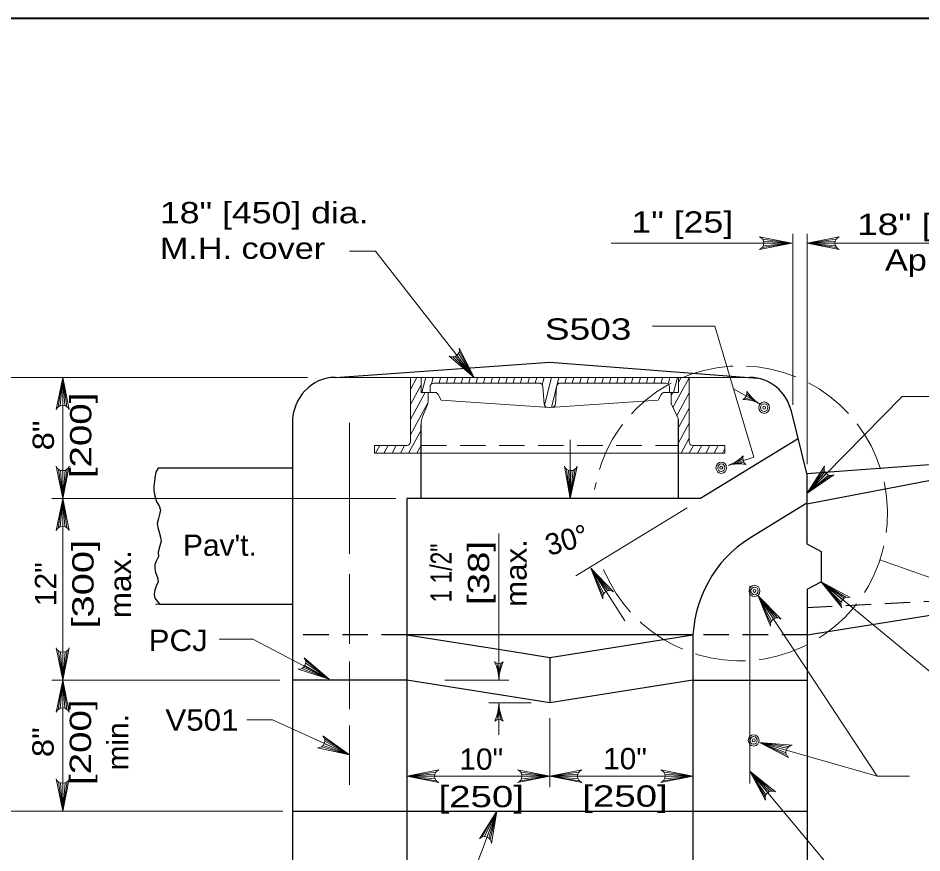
# Model space of a CAD drawing. Extents: x 339.1 to 373.1, y 1412.7 to 1456.7.
# Drawn here: x 342.65 to 349.27, y 1428.13 to 1434.25 of the extents above; entities that cross this region are included whole.
import ezdxf
from ezdxf.enums import TextEntityAlignment as Align

# ---------------------------------------------------------------- set-up
doc = ezdxf.new("R2010")
doc.units = 0
doc.header["$LTSCALE"] = 0.062
doc.linetypes.add('LONG_DASHED', pattern=[7.5, 6, -1.5])
doc.linetypes.add('MEDIUM_DASHED', pattern=[4.5, 3, -1.5])
doc.layers.add('1', color=7, linetype='Continuous', lineweight=13)

msp = doc.modelspace()

# ---------------------------------------------------------------- linework, layer by layer
at = {"layer": '1', "lineweight": 25}
for p, q in [((341.0605, 1434.2455), (372.5605, 1434.2455)), ((344.96875, 1431.61425), (346.53958, 1431.72508)), ((346.53958, 1431.72508), (348.06092, 1431.609)), ((348.42217, 1430.91067), (348.309, 1431.36625)), ((344.65467, 1431.28167), (344.65467, 1430.23983)), ((347.48167, 1430.72742), (347.48167, 1431.30608)), ((345.597, 1430.72742), (345.597, 1431.27)), ((348.35358, 1431.16217), (347.64233, 1430.72742)), ((348.42217, 1430.68892), (350.30792, 1431.04758)), ((348.42217, 1430.91067), (350.30792, 1431.04758)), ((344.65467, 1430.94908), (343.67008, 1430.94908)), ((348.42217, 1430.91067), (348.42217, 1430.39483)), ((345.49225, 1430.72742), (345.49225, 1426.24892)), ((347.64233, 1430.72742), (345.49225, 1430.72742)), ((348.42217, 1430.69225), (348.005, 1430.43717)), ((348.42217, 1430.39483), (348.52783, 1430.339)), ((348.52783, 1430.339), (348.52783, 1430.11725)), ((348.424, 1430.06225), (348.52783, 1430.11725)), ((348.424, 1430.06225), (348.424, 1425.36217)), ((348.424, 1429.72975), (350.30775, 1430.02767)), ((344.65467, 1429.95142), (343.68225, 1429.95142)), ((346.53925, 1429.56342), (347.58642, 1429.72975)), ((346.53925, 1429.56342), (346.53925, 1429.23092)), ((345.49225, 1429.39717), (344.65433, 1429.39717)), ((346.53933, 1429.23092), (345.49225, 1429.39717)), ((347.58642, 1429.39717), (346.53925, 1429.23092)), ((347.58642, 1429.39717), (348.42417, 1429.39717)), ((344.65467, 1428.43842), (348.424, 1428.43842))]:
    msp.add_line(p, q, dxfattribs=at)
at = {"layer": '1'}
for p, q in [((348.098, 1432.62742), (348.31125, 1432.59758)), ((348.10517, 1432.61267), (348.31125, 1432.59758)), ((348.31933, 1431.41267), (348.31933, 1432.665)), ((348.424, 1430.9775), (348.424, 1432.665)), ((348.63733, 1432.62742), (348.424, 1432.59758)), ((348.63008, 1432.61267), (348.424, 1432.59758)), ((346.99033, 1432.59758), (348.31125, 1432.59758)), ((348.0955, 1432.56458), (348.31125, 1432.59758)), ((348.10367, 1432.57842), (348.31125, 1432.59758)), ((348.10742, 1432.59758), (348.31125, 1432.59758)), ((348.424, 1432.59758), (349.80033, 1432.59758)), ((348.62792, 1432.59758), (348.424, 1432.59758)), ((348.63167, 1432.57842), (348.424, 1432.59758)), ((348.63983, 1432.56458), (348.424, 1432.59758)), ((347.74825, 1431.99017), (347.29283, 1431.99017)), ((348.03492, 1431.02983), (347.74825, 1431.99017)), ((345.82975, 1431.76392), (345.98458, 1431.61425)), ((345.84583, 1431.76733), (345.98458, 1431.61425)), ((345.85908, 1431.77483), (345.98458, 1431.61425)), ((345.87183, 1431.78967), (345.98458, 1431.61425)), ((345.87775, 1431.80458), (345.98458, 1431.61425)), ((344.76575, 1431.61425), (342.21133, 1431.61425)), ((342.93883, 1431.39842), (342.97183, 1431.61425)), ((342.95267, 1431.40658), (342.97183, 1431.61425)), ((342.97183, 1430.94633), (342.97183, 1431.61425)), ((342.97183, 1431.41033), (342.97183, 1431.61425)), ((342.98683, 1431.40817), (342.97183, 1431.61425)), ((343.00167, 1431.40092), (342.97183, 1431.61425)), ((348.00525, 1431.61425), (344.96875, 1431.61425)), ((345.5185, 1431.14308), (345.5185, 1431.61425)), ((345.5185, 1431.52658), (345.56633, 1431.61425)), ((345.597, 1431.50342), (345.597, 1431.61425)), ((345.60317, 1431.50342), (345.631, 1431.61333)), ((345.67375, 1431.56767), (345.68558, 1431.61425)), ((345.72917, 1431.57267), (345.73958, 1431.61425)), ((345.78333, 1431.57267), (345.79392, 1431.61425)), ((345.8375, 1431.57267), (345.848, 1431.61425)), ((345.89167, 1431.57267), (345.90217, 1431.61425)), ((345.94583, 1431.57267), (345.95633, 1431.61425)), ((346.00008, 1431.57267), (346.01058, 1431.61425)), ((346.05425, 1431.57267), (346.06483, 1431.61425)), ((346.10833, 1431.57267), (346.11892, 1431.61425)), ((346.16258, 1431.57267), (346.17317, 1431.61425)), ((346.21683, 1431.57267), (346.22742, 1431.61425)), ((346.27108, 1431.57267), (346.28158, 1431.61425)), ((346.32525, 1431.57267), (346.33575, 1431.61425)), ((346.37942, 1431.57267), (346.39, 1431.61433)), ((346.43367, 1431.57267), (346.44425, 1431.61425)), ((346.48475, 1431.55992), (346.49833, 1431.61358)), ((346.50083, 1431.40975), (346.5525, 1431.61392)), ((346.55117, 1431.39433), (346.60633, 1431.61233)), ((346.6505, 1431.57267), (346.661, 1431.61425)), ((346.70458, 1431.57267), (346.71517, 1431.61425)), ((346.759, 1431.57267), (346.7695, 1431.61425)), ((346.81317, 1431.57267), (346.82358, 1431.61425)), ((346.86717, 1431.57267), (346.87775, 1431.61425)), ((346.9215, 1431.57267), (346.932, 1431.61425)), ((346.97575, 1431.57267), (346.98625, 1431.61425)), ((347.03, 1431.57267), (347.04042, 1431.61425)), ((347.08408, 1431.57267), (347.09467, 1431.61425)), ((347.13833, 1431.57267), (347.14892, 1431.61425)), ((347.1925, 1431.57267), (347.203, 1431.61375)), ((347.24675, 1431.57267), (347.25692, 1431.61292)), ((347.30075, 1431.57267), (347.31133, 1431.61425)), ((347.355, 1431.57267), (347.3655, 1431.614)), ((347.40742, 1431.56567), (347.41958, 1431.61358)), ((347.44158, 1431.39417), (347.56025, 1431.6115)), ((347.44592, 1431.50342), (347.47392, 1431.61425)), ((347.48167, 1431.50342), (347.48167, 1431.61425)), ((347.48167, 1431.57875), (347.50108, 1431.61425)), ((347.56025, 1431.14308), (347.56025, 1431.61425)), ((345.5185, 1431.41558), (345.597, 1431.5595)), ((345.66242, 1431.50342), (345.66242, 1431.54492)), ((346.46267, 1431.57267), (345.68858, 1431.57267)), ((346.48883, 1431.54708), (346.49817, 1431.41817)), ((346.58983, 1431.54708), (346.5805, 1431.41817)), ((347.39008, 1431.57267), (346.616, 1431.57267)), ((347.41625, 1431.50342), (347.41625, 1431.54492)), ((345.5185, 1431.30483), (345.62683, 1431.50342)), ((345.69967, 1431.50342), (345.597, 1431.50342)), ((345.64933, 1431.4595), (345.64933, 1431.50342)), ((345.72233, 1431.4895), (345.74508, 1431.44792)), ((347.35633, 1431.4895), (347.33367, 1431.44792)), ((347.48167, 1431.50342), (347.37917, 1431.50342)), ((347.42933, 1431.42358), (347.42933, 1431.50342)), ((347.42975, 1431.48342), (347.44008, 1431.5025)), ((347.46967, 1431.33492), (347.56025, 1431.50075)), ((348.08, 1431.4195), (347.88575, 1431.52958)), ((345.5185, 1431.19408), (345.64675, 1431.429)), ((345.74508, 1431.44792), (346.53767, 1431.39367)), ((347.33367, 1431.44792), (346.541, 1431.39367)), ((347.43067, 1431.41733), (347.48033, 1431.31225)), ((345.63283, 1431.38508), (345.61367, 1431.3445)), ((347.48167, 1431.24608), (347.56025, 1431.39)), ((345.0735, 1431.28167), (345.0735, 1430.32158)), ((347.48167, 1431.13525), (347.56025, 1431.27908)), ((345.50575, 1431.06), (345.597, 1431.227)), ((346.689, 1430.72742), (346.689, 1431.15717)), ((347.50108, 1431.06), (347.56025, 1431.16842)), ((345.25667, 1431.06), (345.25667, 1431.11542)), ((345.49225, 1431.11542), (345.25667, 1431.11542)), ((345.264, 1431.06), (345.29425, 1431.11542)), ((345.32442, 1431.06), (345.35467, 1431.11542)), ((345.38483, 1431.06), (345.41508, 1431.11542)), ((345.44525, 1431.06), (345.4755, 1431.11542)), ((345.56608, 1431.06), (345.597, 1431.1165)), ((347.56158, 1431.06), (347.59183, 1431.11542)), ((347.822, 1431.11542), (347.58642, 1431.11542)), ((347.622, 1431.06), (347.65225, 1431.11542)), ((347.6825, 1431.06), (347.71275, 1431.11542)), ((347.74292, 1431.06), (347.77317, 1431.11542)), ((347.80358, 1431.06042), (347.822, 1431.09425)), ((347.822, 1431.06), (347.822, 1431.11542)), ((347.822, 1431.06), (345.25667, 1431.06)), ((347.84567, 1430.96975), (348.03492, 1431.02983)), ((342.94192, 1430.94067), (342.97183, 1430.72742)), ((342.95675, 1430.9335), (342.97183, 1430.72742)), ((343.00475, 1430.94325), (342.97183, 1430.72742)), ((342.991, 1430.935), (342.97183, 1430.72742)), ((342.97183, 1430.93125), (342.97183, 1430.72742)), ((346.66308, 1430.94125), (346.689, 1430.72742)), ((346.67775, 1430.93375), (346.689, 1430.72742)), ((346.726, 1430.94258), (346.689, 1430.72742)), ((346.712, 1430.93467), (346.689, 1430.72742)), ((346.69275, 1430.93125), (346.689, 1430.72742)), ((348.54967, 1430.93717), (348.42217, 1430.76358)), ((348.55517, 1430.92167), (348.42217, 1430.76358)), ((348.56442, 1430.90958), (348.42217, 1430.76358)), ((348.58075, 1430.89892), (348.42217, 1430.76358)), ((348.59642, 1430.89517), (348.42217, 1430.76358)), ((345.41283, 1430.72742), (342.89317, 1430.72742)), ((342.93883, 1430.51158), (342.97183, 1430.72742)), ((342.95267, 1430.51975), (342.97183, 1430.72742)), ((342.97183, 1430.52358), (342.97183, 1430.72742)), ((342.98683, 1430.52133), (342.97183, 1430.72742)), ((343.00167, 1430.51408), (342.97183, 1430.72742)), ((347.54517, 1430.65842), (346.73083, 1430.16058)), ((346.16733, 1429.39717), (346.16733, 1430.47133)), ((346.95017, 1430.04558), (346.8405, 1430.21742)), ((346.93608, 1430.03208), (346.8405, 1430.21742)), ((346.92883, 1430.01775), (346.8405, 1430.21742)), ((346.96408, 1430.05183), (346.8405, 1430.21742)), ((346.98042, 1430.05367), (346.8405, 1430.21742)), ((348.95742, 1430.277), (351.58392, 1429.34875)), ((345.0735, 1430.172), (345.0735, 1429.66358)), ((346.84392, 1430.21392), (347.08983, 1429.83042)), ((348.00525, 1430.08842), (348.00525, 1429.44708)), ((348.68392, 1429.98617), (348.52775, 1430.11717)), ((348.6745, 1429.96908), (348.52775, 1430.11717)), ((348.67192, 1429.95325), (348.52775, 1430.11717)), ((348.69533, 1429.99633), (348.52775, 1430.11717)), ((348.71033, 1430.003), (348.52775, 1430.11717)), ((348.17817, 1429.84492), (348.066, 1430.01525)), ((348.16417, 1429.83125), (348.066, 1430.01525)), ((348.15717, 1429.81683), (348.066, 1430.01525)), ((348.19192, 1429.85142), (348.066, 1430.01525)), ((348.20825, 1429.8535), (348.066, 1430.01525)), ((342.94192, 1429.6105), (342.97183, 1429.39717)), ((342.95675, 1429.60325), (342.97183, 1429.39717)), ((343.00475, 1429.613), (342.97183, 1429.39717)), ((342.991, 1429.60483), (342.97183, 1429.39717)), ((342.97183, 1429.601), (342.97183, 1429.39717)), ((344.73683, 1429.49183), (344.92425, 1429.40483)), ((344.74608, 1429.50392), (344.92425, 1429.40483)), ((344.75167, 1429.5385), (344.92425, 1429.40483)), ((344.75208, 1429.5225), (344.92425, 1429.40483)), ((345.0735, 1429.534), (345.0735, 1429.185)), ((348.00525, 1429.48967), (348.00525, 1428.64075)), ((344.72333, 1429.48242), (344.92425, 1429.40483)), ((344.56117, 1429.39717), (342.89317, 1429.39717)), ((342.93883, 1429.18142), (342.97183, 1429.39717)), ((342.95267, 1429.1895), (342.97183, 1429.39717)), ((342.97183, 1429.19333), (342.97183, 1429.39717)), ((342.98683, 1429.19108), (342.97183, 1429.39717)), ((343.00167, 1429.18392), (342.97183, 1429.39717)), ((344.65433, 1429.39717), (344.65183, 1429.39717)), ((346.23925, 1429.39717), (345.7715, 1429.39717)), ((346.40267, 1429.23092), (346.092, 1429.23092)), ((346.16733, 1428.99658), (346.16733, 1429.23092)), ((346.53933, 1429.11842), (346.53933, 1428.61267)), ((345.0735, 1429.06542), (345.0735, 1428.63067)), ((344.88992, 1428.96725), (345.0735, 1428.84908)), ((344.86658, 1428.90892), (345.0735, 1428.84908)), ((344.87917, 1428.91942), (345.0735, 1428.84908)), ((344.88733, 1428.93225), (345.0735, 1428.84908)), ((344.89175, 1428.95133), (345.0735, 1428.84908)), ((348.27142, 1428.88433), (348.0755, 1428.94067)), ((348.26975, 1428.86483), (348.0755, 1428.94067)), ((348.27383, 1428.84933), (348.0755, 1428.94067)), ((348.27775, 1428.89825), (348.0755, 1428.94067)), ((348.28875, 1428.91042), (348.0755, 1428.94067)), ((348.0755, 1428.94067), (348.93842, 1428.69425)), ((345.70558, 1428.72367), (345.49225, 1428.69383)), ((345.69833, 1428.70892), (345.49225, 1428.69383)), ((346.32608, 1428.72367), (346.53933, 1428.69383)), ((346.33325, 1428.70892), (346.53933, 1428.69383)), ((346.75258, 1428.72367), (346.53933, 1428.69383)), ((346.74542, 1428.70892), (346.53933, 1428.69383)), ((347.37417, 1428.72367), (347.58742, 1428.69383)), ((347.38142, 1428.70892), (347.58742, 1428.69383)), ((348.1355, 1428.57342), (348.00525, 1428.73017)), ((348.12317, 1428.55825), (348.00525, 1428.73017)), ((348.11775, 1428.54317), (348.00525, 1428.73017)), ((348.1485, 1428.58133), (348.00525, 1428.73017)), ((348.1645, 1428.58525), (348.00525, 1428.73017)), ((342.94192, 1428.65167), (342.97183, 1428.43842)), ((342.95675, 1428.6445), (342.97183, 1428.43842)), ((343.00475, 1428.65417), (342.97183, 1428.43842)), ((342.991, 1428.646), (342.97183, 1428.43842)), ((342.97183, 1428.64225), (342.97183, 1428.43842)), ((345.49225, 1428.69383), (346.36317, 1428.69383)), ((345.69617, 1428.69383), (345.49225, 1428.69383)), ((345.69992, 1428.67467), (345.49225, 1428.69383)), ((345.70808, 1428.66083), (345.49225, 1428.69383)), ((346.3235, 1428.66083), (346.53933, 1428.69383)), ((346.33167, 1428.67467), (346.53933, 1428.69383)), ((346.3355, 1428.69383), (346.53933, 1428.69383)), ((346.74317, 1428.69383), (346.53933, 1428.69383)), ((346.747, 1428.67467), (346.53933, 1428.69383)), ((346.75517, 1428.66083), (346.53933, 1428.69383)), ((347.20875, 1428.69383), (347.58742, 1428.69383)), ((347.37167, 1428.66083), (347.58742, 1428.69383)), ((347.37983, 1428.67467), (347.58742, 1428.69383)), ((347.38358, 1428.69383), (347.58742, 1428.69383)), ((344.58483, 1428.43842), (342.21133, 1428.43842)), ((346.15242, 1428.43842), (345.98342, 1427.99108)), ((346.0445, 1428.24867), (346.15242, 1428.43842)), ((346.06033, 1428.25133), (346.15242, 1428.43842)), ((346.07958, 1428.248), (346.15242, 1428.43842)), ((346.09292, 1428.24058), (346.15242, 1428.43842)), ((346.10408, 1428.22858), (346.15242, 1428.43842))]:
    msp.add_line(p, q, dxfattribs=at)
at = {"layer": '1', "linetype": 'MEDIUM_DASHED'}
msp.add_line((345.597, 1431.11542), (347.48167, 1431.11542), dxfattribs=at)
at = {"layer": '1', "linetype": 'MEDIUM_DASHED', "lineweight": 25}
for p, q in [((348.42208, 1429.92925), (350.30775, 1430.02767)), ((345.49225, 1429.72975), (344.65467, 1429.72975)), ((348.424, 1429.72975), (347.58642, 1429.72975))]:
    msp.add_line(p, q, dxfattribs=at)
at = {"layer": '1', "lineweight": 40}
msp.add_lwpolyline([(341.0605, 1434.2455), (372.5605, 1434.2455), (372.5605, 1413.2455), (341.0605, 1413.2455)], close=True, dxfattribs=at)
at = {"layer": '1'}
for points in [[(348.07567, 1432.55042), (348.31125, 1432.59758), (348.07567, 1432.64467)], [(348.65958, 1432.55042), (348.424, 1432.59758), (348.65958, 1432.64467)], [(345.98458, 1431.61425), (345.26242, 1432.5385), (345.0735, 1432.5385)], [(345.87667, 1431.82892), (345.98458, 1431.61425), (345.80242, 1431.77083)], [(342.92467, 1431.37867), (342.97183, 1431.61425), (343.01892, 1431.37867)], [(348.42217, 1430.76358), (349.12, 1431.47433), (349.33642, 1431.47433)], [(343.01892, 1430.963), (342.97183, 1430.72742), (342.92467, 1430.963)], [(342.97183, 1428.43842), (342.97183, 1429.39717), (342.97183, 1430.72742), (342.97183, 1430.97317)], [(346.7405, 1430.96208), (346.689, 1430.72742), (346.64625, 1430.96383)], [(348.62033, 1430.89942), (348.42217, 1430.76358), (348.55283, 1430.96517)], [(342.92467, 1430.49183), (342.97183, 1430.72742), (343.01892, 1430.49183)], [(346.92758, 1429.9935), (346.8405, 1430.21742), (347.007, 1430.04417)], [(348.52658, 1430.11658), (349.46492, 1429.34283), (349.61083, 1429.34283)], [(348.678, 1429.92967), (348.52775, 1430.11717), (348.7385, 1430.00192)], [(348.15625, 1429.7925), (348.066, 1430.01525), (348.23492, 1429.84433)], [(348.066, 1430.01525), (348.93842, 1428.69425), (349.17308, 1428.69425)], [(344.92425, 1429.40483), (344.3655, 1429.69742), (344.11858, 1429.69742)], [(343.01892, 1429.63275), (342.97183, 1429.39717), (342.92467, 1429.63275)], [(344.74125, 1429.5605), (344.92425, 1429.40483), (344.69542, 1429.47817)], [(342.92467, 1429.16158), (342.97183, 1429.39717), (343.01892, 1429.16158)], [(345.0735, 1428.84908), (344.50842, 1429.10625), (344.32, 1429.10625)], [(344.87758, 1428.98825), (345.0735, 1428.84908), (344.83917, 1428.90217)], [(348.28892, 1428.83025), (348.0755, 1428.94067), (348.31492, 1428.92083)], [(345.72783, 1428.64667), (345.49225, 1428.69383), (345.72783, 1428.74092)], [(346.30375, 1428.64667), (346.53933, 1428.69383), (346.30375, 1428.74092)], [(346.77492, 1428.64667), (346.53933, 1428.69383), (346.77492, 1428.74092)], [(347.35183, 1428.64667), (347.58742, 1428.69383), (347.35183, 1428.74092)], [(348.11958, 1428.51892), (348.00525, 1428.73017), (348.192, 1428.57917)], [(348.00525, 1428.73017), (349.03675, 1427.48925), (349.26192, 1427.48925)], [(343.01892, 1428.674), (342.97183, 1428.43842), (342.92467, 1428.674)], [(346.21, 1428.69383), (346.53933, 1428.69383), (347.22825, 1428.69383)], [(346.02425, 1428.23525), (346.15242, 1428.43842), (346.11225, 1428.2015)]]:
    msp.add_lwpolyline(points, dxfattribs=at)
at = {"layer": '1', "lineweight": 25}
for points in [[(343.67008, 1430.94908), (343.6545, 1430.919), (343.64575, 1430.88217), (343.644, 1430.84908), (343.6405, 1430.81975), (343.6405, 1430.7885), (343.644, 1430.75542), (343.65967, 1430.704), (343.67875, 1430.67283), (343.68742, 1430.64158), (343.68042, 1430.61033), (343.6735, 1430.581), (343.66317, 1430.54425), (343.66825, 1430.51492), (343.67875, 1430.48183), (343.68908, 1430.44508), (343.69258, 1430.41392), (343.684, 1430.38075), (343.67008, 1430.33492), (343.6735, 1430.30358), (343.65967, 1430.27425), (343.64575, 1430.24483), (343.64758, 1430.21375), (343.65267, 1430.18433), (343.66658, 1430.14758), (343.67008, 1430.11642), (343.65617, 1430.08517), (343.64575, 1430.05575), (343.64233, 1430.02633), (343.64575, 1429.997), (343.68225, 1429.95142), (343.6545, 1429.95292), (343.65617, 1429.95292)], [(344.65467, 1430.23983), (344.65467, 1428.43842), (344.65467, 1427.77333)], [(347.58642, 1429.72975), (346.259, 1429.72975), (345.49225, 1429.72975), (346.25667, 1429.60833), (346.53925, 1429.56342)], [(347.58642, 1429.66925), (347.58642, 1428.85175), (347.58642, 1426.24892)]]:
    msp.add_lwpolyline(points, dxfattribs=at)
at = {"layer": '1'}
for centre, start, end in [((348.05665, 1432.59761), 292.08605, 67.91218), ((348.67864, 1432.59761), 112.08782, 247.91395), ((345.8278, 1431.81483), 240.09077, 15.9169), ((342.97185, 1431.35961), 22.08782, 157.91395), ((342.97174, 1430.98202), 202.08782, 337.91395), ((346.69367, 1430.98198), 201.01792, 336.84405), ((348.59982, 1430.94598), 157.82535, 293.65148), ((342.97185, 1430.47279), 22.08782, 157.91395), ((346.97755, 1430.0028), 54.6311, 190.45723), ((348.72286, 1429.95362), 72.09994, 207.92607), ((348.20609, 1429.80258), 55.44695, 191.27308), ((342.97174, 1429.65178), 202.08782, 337.91395), ((344.70166, 1429.52852), 263.02075, 38.84688), ((342.97185, 1429.14256), 22.08782, 157.91395), ((344.841, 1428.95294), 268.00337, 43.82949), ((348.32023, 1428.87036), 96.05502, 231.88114), ((345.7469, 1428.69387), 112.08782, 247.91395), ((346.28472, 1428.69387), 292.08605, 67.91218), ((346.79395, 1428.69387), 112.08782, 247.91395), ((347.33282, 1428.69387), 292.08605, 67.91218), ((342.97174, 1428.69302), 202.08782, 337.91395), ((348.16801, 1428.53442), 61.8219, 197.64803), ((346.0615, 1428.20059), 1.14701, 136.97314)]:
    msp.add_arc(centre, 0.05085, start, end, dxfattribs=at)
at = {"layer": '1', "linetype": 'LONG_DASHED'}
msp.add_arc((347.93338, 1430.61799), 1.08003, 202.3105, 170.63217, dxfattribs=at)
at = {"layer": '1', "lineweight": 25}
for centre, major_axis, start_param, end_param in [((344.96876, 1431.28167), (0, 0.33256), 6.2831853, 7.8539816), ((348.00521, 1431.28167), (0, 0.33256), 4.9695769, 6.2831854), ((348.42403, 1429.66926), (0, 0.88682), 0.5238421, 1.5707963)]:
    msp.add_ellipse(centre, major_axis=major_axis, ratio=0.944544, start_param=start_param, end_param=end_param, dxfattribs=at)
at = {"layer": '1'}
for centre, major_axis, ratio, start_param, end_param in [((345.6886, 1431.54495), (0, 0.02771), 0.944544, 6.2831853, 7.8539815), ((346.46274, 1431.54495), (0, 0.02771), 0.944544, 4.7891608, 6.2831853), ((346.61593, 1431.54495), (0, 0.02771), 0.944544, 0, 1.4940245), ((347.39007, 1431.54495), (0, 0.02771), 0.944544, 4.712389, 6.2831853), ((345.69968, 1431.47566), (0, 0.02771), 0.944544, 5.2364748, 6.2831853), ((347.37901, 1431.47566), (0, 0.02771), 0.944544, 0, 1.0473532), ((347.9326, 1431.50288), (0, 0.05499), 0.944544, 3.5712986, 4.8702888), ((348.1481, 1431.54805), (0.24046, -0.14909), 0.514061, 4.3110239, 4.7468861), ((348.21402, 1431.67814), (0, -0.29516), 0.944544, 5.3121958, 5.7810271), ((345.49228, 1431.45949), (0, 0.16628), 0.944544, 4.2487414, 4.712389), ((346.52414, 1431.42234), (0, -0.02771), 0.944544, 4.7887663, 6.2185509), ((346.55454, 1431.42234), (0, -0.02771), 0.944544, 0.0646344, 1.494419), ((347.44242, 1431.42351), (0, 0.01386), 0.944544, 1.5707963, 2.0344439), ((347.95236, 1431.16322), (0, 0.28968), 0.944544, 5.7979781, 6.2763346), ((348.01651, 1431.28785), (-0.24631, 0.138), 0.516235, 4.7422466, 5.180714), ((345.75405, 1431.27008), (0, 0.16628), 0.944544, 1.1065632, 1.5707963), ((346.53934, 1431.42129), (0, -0.02771), 0.944544, 6.218551, 6.3478196), ((347.4686, 1431.30611), (0, 0.01386), 0.944544, 4.712389, 5.1760366), ((345.49228, 1431.14311), (0, 0.02771), 0.944544, 3.1415928, 4.712389), ((347.58639, 1431.14311), (0, 0.02771), 0.944544, 1.5707963, 3.1415926), ((347.80292, 1431.11041), (0.26416, 0.09413), 0.523262, 4.6856737, 5.1241411), ((347.76533, 1431.24665), (0, -0.28968), 0.944544, 0.2978854, 0.776242), ((348.00567, 1431.02068), (0, -0.05499), 0.944544, 4.3543913, 5.6533815), ((347.88303, 1430.82771), (-0.2678, -0.08184), 0.524768, 4.255611, 4.6914731), ((347.92301, 1430.68628), (0, 0.29516), 0.944544, 6.0952884, 6.5641197), ((346.16721, 1429.5741), (0, -0.05499), 0.944544, 5.6336903, 6.9326805), ((345.89371, 1429.39532), (0, 0.28968), 0.944544, 4.718777, 5.1971336), ((346.02777, 1429.39428), (-0.00568, 0.29509), 0.472393, 4.7112233, 5.1496908), ((346.30655, 1429.39428), (-0.00568, -0.29509), 0.472393, 4.2754323, 4.7112945), ((346.44599, 1429.39417), (0, 0.29516), 0.944544, 1.0914021, 1.5602334), ((345.88864, 1429.2339), (0, -0.29516), 0.944544, 1.0914021, 1.5602334), ((346.02809, 1429.23379), (0.00568, 0.29509), 0.472393, 4.2754323, 4.7112945), ((346.44093, 1429.23275), (0, -0.28968), 0.944544, 4.718777, 5.1971336), ((346.30686, 1429.23379), (0.00568, -0.29509), 0.472393, 4.7112233, 5.1496908), ((346.16742, 1429.05397), (0, 0.05499), 0.944544, 5.6336903, 6.9326805)]:
    msp.add_ellipse(centre, major_axis=major_axis, ratio=ratio, start_param=start_param, end_param=end_param, dxfattribs=at)
for centre, major_axis in [((348.10992, 1431.39252), (0, 0.04157)), ((348.10992, 1431.39252), (0, 0.02771)), ((348.10992, 1431.39252), (0, 0.01109)), ((347.7958, 1430.95244), (0, 0.04157)), ((347.7958, 1430.95244), (0, 0.02771)), ((347.7958, 1430.95244), (0, 0.01109)), ((348.03945, 1430.05043), (0, 0.04157)), ((348.03945, 1430.05043), (0, 0.02771)), ((348.03945, 1430.05043), (0, 0.01109)), ((348.03306, 1428.95609), (0, 0.04157)), ((348.03306, 1428.95609), (0, 0.02771)), ((348.03306, 1428.95609), (0, 0.01109))]:
    msp.add_ellipse(centre, major_axis=major_axis, ratio=0.944544, dxfattribs=at)

# ---------------------------------------------------------------- texts
for s, width, p in [('18" [450] dia.', 1.25, (343.68392, 1432.74283)), ('M.H. cover', 1.2, (343.68392, 1432.48217)), ('S503', 1.3, (346.50367, 1431.89017)), ("Pav't.", 1.05, (343.85292, 1430.30742)), ('V501', 1.1, (343.72392, 1429.02725))]:
    msp.add_text(s, height=0.156, dxfattribs=dict(at, width=width)).set_placement(p)
for s, width, p in [('1" [25]', 1.25, (347.51008, 1432.67392)), ('18" [450]', 1.3, (349.32867, 1432.657)), ('Apron', 1.2, (349.32879, 1432.39633)), ('PCJ', 1.1, (343.81788, 1429.61033)), ('10"', 1.05, (346.03746, 1428.7405)), ('10"', 1.05, (347.09037, 1428.74425)), ('[250]', 1.35, (346.03754, 1428.4665)), ('[250]', 1.35, (347.09046, 1428.47025))]:
    msp.add_text(s, height=0.156, dxfattribs=dict(at, width=width)).set_placement(p, align=Align.CENTER)
for s, width, p in [('[200]', 1.35, (343.18167, 1431.18937)), ('8"', 1.15, (342.90767, 1431.18929)), ('[300]', 1.4, (343.19817, 1430.09971)), ('1 1/2"', 0.8, (345.82183, 1430.18158)), ('[38]', 1.35, (346.09583, 1430.18154)), ('max.', 1.1, (346.36983, 1430.18162)), ('max.', 1.1, (343.47217, 1430.09962)), ('12"', 1.05, (342.92417, 1430.09971)), ('[200]', 1.35, (343.1795, 1428.94254)), ('min.', 1.05, (343.4535, 1428.94246)), ('8"', 1.15, (342.9055, 1428.94254))]:
    msp.add_text(s, height=0.156, rotation=90, dxfattribs=dict(at, width=width)).set_placement(p, align=Align.CENTER)
msp.add_text('30°', height=0.156, rotation=15.838, dxfattribs=at).set_placement((346.53275, 1430.306))

doc.saveas('drawing.dxf')
